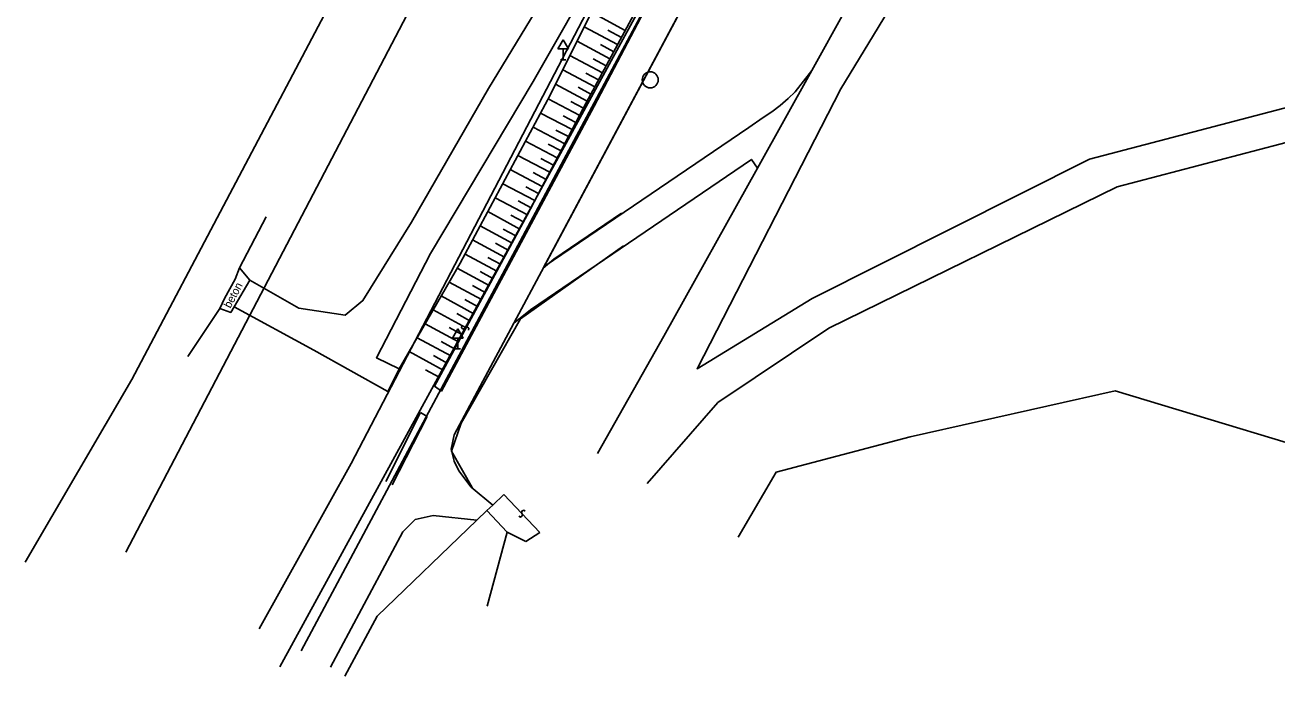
# Model space of a CAD drawing. Extents: x -747268 to -747068, y -964730 to -964532.
# Drawn here: x -747267.8 to -747150.9, y -964730 to -964669.2 of the extents above; entities that cross this region are included whole.
import ezdxf

# ---------------------------------------------------------------- set-up
doc = ezdxf.new("R2010")
doc.units = 0
for name, color, linetype in [('Bonity', 7, 'Continuous'), ('Obvody budov', 7, 'Continuous'), ('Vrstva 15', 7, 'Continuous'), ('Vrstva 16', 7, 'Continuous'), ('Vrstva 20', 7, 'Continuous'), ('Vrstva 27', 7, 'Continuous'), ('Vrstva 28', 7, 'Continuous')]:
    doc.layers.add(name, color=color, linetype=linetype)

msp = doc.modelspace()

# ---------------------------------------------------------------- linework, layer by layer
at = {"layer": 'Bonity'}
msp.add_lwpolyline([(-747212.14, -964686.73), (-747218.44, -964691.02)], dxfattribs=at)
at = {"layer": 'Obvody budov'}
for p, q in [((-747217.58, -964670.52), (-747218.08, -964671.39)), ((-747217.58, -964670.52), (-747217.08, -964671.39)), ((-747218.08, -964671.39), (-747217.08, -964671.39)), ((-747217.58, -964672.39), (-747217.58, -964671.39)), ((-747217.83, -964672.39), (-747217.33, -964672.39)), ((-747227.41, -964697.54), (-747227.91, -964698.41)), ((-747227.41, -964697.54), (-747226.91, -964698.41)), ((-747227.91, -964698.41), (-747226.91, -964698.41)), ((-747227.41, -964699.41), (-747227.41, -964698.41)), ((-747227.66, -964699.41), (-747227.16, -964699.41))]:
    msp.add_line(p, q, dxfattribs=at)
msp.add_circle((-747209.45, -964674.27), 0.75, dxfattribs=at)
at = {"layer": 'Vrstva 15'}
for points in [[(-747164.8, -964581.46), (-747168.98, -964589.75), (-747182.91, -964616.97), (-747186.63, -964624.1), (-747193.85, -964638.28), (-747194.38, -964638.56), (-747199.08, -964647.44), (-747204.82, -964658.33), (-747208.77, -964665.45), (-747214.7, -964676.73), (-747220.35, -964687.31), (-747228.95, -964703.36)], [(-747207.74, -964618.01), (-747209.42, -964620.7), (-747207.13, -964621.42), (-747205.64, -964619.2), (-747202.99, -964624.62), (-747199.45, -964632.07), (-747215.93, -964660.89), (-747224.57, -964675.08), (-747231.76, -964687.56), (-747236.28, -964694.89), (-747237.94, -964696.27), (-747242.26, -964695.59), (-747246.85, -964693), (-747247.82, -964691.84), (-747248.23, -964692.9)], [(-747212.14, -964686.73), (-747218.44, -964691.02), (-747219.46, -964691.87), (-747209.93, -964674.01), (-747202.82, -964660.7), (-747201.3, -964658.87), (-747199.71, -964658.58), (-747200.02, -964667.66)], [(-747232.9, -964701.27), (-747235.02, -964700.23), (-747229.96, -964690.49), (-747220.4, -964674.42), (-747214, -964663.21), (-747212.54, -964663.12)], [(-747226.09, -964712.35), (-747228.02, -964708.96), (-747227.1, -964706.36), (-747221.56, -964696.59), (-747211.96, -964689.78)], [(-747248.23, -964692.9), (-747249.2, -964694.71)], [(-747248.32, -964695.49), (-747246.85, -964693)], [(-747249.2, -964694.71), (-747249.65, -964695.64), (-747248.63, -964696), (-747248.32, -964695.49), (-747240.87, -964699.52), (-747233.96, -964703.39)], [(-747233.96, -964703.39), (-747232.9, -964701.27)], [(-747228.95, -964703.36), (-747229.61, -964702.9)], [(-747230.28, -964705.73), (-747233.55, -964712.11)], [(-747230.28, -964705.73), (-747230.91, -964705.35)]]:
    msp.add_lwpolyline(points, dxfattribs=at)
at = {"layer": 'Vrstva 16'}
for points in [[(-747232.9, -964701.27), (-747227.21, -964691.41), (-747218.79, -964675.69), (-747212.54, -964663.12)], [(-747209.31, -964665.03), (-747215.42, -964676.41), (-747220.94, -964686.92), (-747229.61, -964702.9)], [(-747211.79, -964669.66), (-747214.95, -964667.96)], [(-747212.5, -964670.98), (-747215.62, -964669.31)], [(-747213.21, -964672.3), (-747216.28, -964670.65)], [(-747212.15, -964670.32), (-747213.4, -964669.64)], [(-747212.86, -964671.64), (-747214.09, -964670.97)], [(-747213.92, -964673.62), (-747216.95, -964671.99)], [(-747213.57, -964672.96), (-747214.79, -964672.3)], [(-747214.63, -964674.94), (-747217.62, -964673.34)], [(-747214.28, -964674.28), (-747215.48, -964673.64)], [(-747215.34, -964676.26), (-747218.29, -964674.68)], [(-747214.99, -964675.6), (-747216.17, -964674.96)], [(-747216.04, -964677.59), (-747218.98, -964676.05)], [(-747215.69, -964676.93), (-747216.87, -964676.31)], [(-747216.74, -964678.92), (-747219.69, -964677.37)], [(-747216.39, -964678.26), (-747217.57, -964677.64)], [(-747217.44, -964680.25), (-747220.4, -964678.69)], [(-747218.13, -964681.57), (-747221.11, -964680.01)], [(-747217.09, -964679.58), (-747218.27, -964678.96)], [(-747217.78, -964680.91), (-747218.97, -964680.29)], [(-747218.83, -964682.9), (-747221.81, -964681.33)], [(-747218.48, -964682.24), (-747219.67, -964681.61)], [(-747219.53, -964684.23), (-747222.52, -964682.66)], [(-747219.18, -964683.57), (-747220.37, -964682.94)], [(-747220.22, -964685.56), (-747223.23, -964683.98)], [(-747219.88, -964684.89), (-747221.08, -964684.26)], [(-747220.92, -964686.89), (-747223.94, -964685.3)], [(-747220.57, -964686.22), (-747221.78, -964685.59)], [(-747221.64, -964688.21), (-747224.62, -964686.58)], [(-747221.28, -964687.55), (-747222.48, -964686.9)], [(-747247.82, -964691.84), (-747245.33, -964687.06)], [(-747222.35, -964689.52), (-747225.33, -964687.91)], [(-747223.07, -964690.84), (-747226.04, -964689.23)], [(-747221.99, -964688.86), (-747223.19, -964688.22)], [(-747223.78, -964692.16), (-747226.75, -964690.55)], [(-747222.71, -964690.18), (-747223.9, -964689.54)], [(-747223.43, -964691.5), (-747224.61, -964690.86)], [(-747224.5, -964693.48), (-747227.47, -964691.86)], [(-747224.14, -964692.82), (-747225.33, -964692.18)], [(-747225.21, -964694.8), (-747228.22, -964693.17)], [(-747224.86, -964694.14), (-747226.05, -964693.49)], [(-747225.93, -964696.12), (-747228.97, -964694.46)], [(-747225.57, -964695.46), (-747226.78, -964694.8)], [(-747249.65, -964695.64), (-747252.63, -964700.13)], [(-747226.65, -964697.43), (-747229.72, -964695.76)], [(-747226.29, -964696.78), (-747227.51, -964696.11)], [(-747227.36, -964698.75), (-747230.47, -964697.06)], [(-747227, -964698.09), (-747228.24, -964697.42)], [(-747228.08, -964700.07), (-747231.22, -964698.36)], [(-747227.72, -964699.41), (-747228.97, -964698.73)], [(-747228.79, -964701.39), (-747231.97, -964699.66)], [(-747228.43, -964700.73), (-747229.7, -964700.04)], [(-747229.15, -964702.05), (-747230.43, -964701.35)], [(-747230.91, -964705.35), (-747234.13, -964711.81)]]:
    msp.add_lwpolyline(points, dxfattribs=at)
at = {"layer": 'Vrstva 27'}
for p, q in [((-747194.37, -964673.41), (-747199.44, -964682.52)), ((-747222.18, -964697), (-747219.36, -964691.72)), ((-747224.7, -964714.51), (-747225.64, -964715.41))]:
    msp.add_line(p, q, dxfattribs=at)
for points in [[(-747258.43, -964718.4), (-747225.89, -964656.18), (-747178.58, -964571.79), (-747161.77, -964542.83)], [(-747245.97, -964725.57), (-747237.39, -964710.13), (-747213.15, -964663.66), (-747212.04, -964661.58), (-747205.52, -964649.38), (-747207.93, -964646.01), (-747172.64, -964585.56), (-747171.18, -964583.16), (-747172.38, -964582.51), (-747172.75, -964582.31), (-747169.52, -964576.73), (-747168.08, -964577.53), (-747165.21, -964574.13), (-747160.86, -964564.14), (-747155.16, -964551.47), (-747155.48, -964551.37), (-747155.09, -964550.12), (-747154.28, -964550.33), (-747154.06, -964549.5), (-747153.36, -964547.04)], [(-747242.05, -964727.61), (-747230.16, -964705.36), (-747208.97, -964665.66), (-747208.88, -964665.32), (-747209.05, -964664.92), (-747208.39, -964663.57), (-747207.91, -964663.49), (-747207.6, -964663.09), (-747199.41, -964647.48), (-747199.14, -964646.95), (-747194.94, -964639.04), (-747194.8, -964638.66), (-747194.08, -964638.4), (-747193.89, -964638.17), (-747178.12, -964607.48), (-747165.52, -964582.92), (-747162.81, -964577.62), (-747161.38, -964574.2), (-747160.49, -964571.42), (-747153.77, -964550.39), (-747154.12, -964550.42), (-747153.81, -964549.44), (-747153.11, -964547.25)], [(-747149.73, -964549.09), (-747149.93, -964549.71), (-747150.35, -964549.8), (-747157.75, -964573.23), (-747158.53, -964575.6), (-747159.7, -964578.37), (-747163.23, -964585.33), (-747175.42, -964609.03), (-747186.84, -964631.22), (-747187.01, -964633.47), (-747185.08, -964635.94), (-747196.29, -964656.98), (-747198.54, -964658.68), (-747199.84, -964658.63), (-747201.84, -964659.38), (-747202.78, -964660.64), (-747203.73, -964662.42), (-747219.36, -964691.72)], [(-747179.78, -964638.67), (-747191.19, -964659.92), (-747188.06, -964662.04), (-747194.37, -964673.41)], [(-747170.03, -964639.52), (-747191.65, -964675.11), (-747205.07, -964701.27), (-747194.33, -964694.71), (-747168.43, -964681.69), (-747141.95, -964674.74), (-747119.57, -964669.71), (-747114.21, -964668.06), (-747110.99, -964665.85), (-747107.13, -964660.6)], [(-747104.3, -964675.97), (-747110.73, -964672.35), (-747113.2, -964673.81), (-747141.15, -964677.79), (-747165.83, -964684.28), (-747192.76, -964697.48), (-747203.13, -964704.43), (-747209.73, -964712)], [(-747219.36, -964691.72), (-747200.23, -964678.71), (-747198.91, -964677.79), (-747198.11, -964677.27), (-747197.31, -964676.67), (-747196.56, -964676.02), (-747195.92, -964675.4), (-747194.37, -964673.41)], [(-747222.18, -964697), (-747220.64, -964695.77), (-747200, -964681.71), (-747199.44, -964682.52)], [(-747199.44, -964682.52), (-747208.18, -964698.23), (-747214.38, -964709.19)], [(-747224.7, -964714.51), (-747224.16, -964714), (-747226.16, -964712.32), (-747227.33, -964710.79), (-747227.75, -964709.91), (-747228.03, -964708.77), (-747227.76, -964707.45), (-747222.18, -964697)], [(-747201.23, -964716.99), (-747197.7, -964710.92), (-747185.17, -964707.62), (-747166.03, -964703.32), (-747141.08, -964710.85), (-747134.49, -964709.31), (-747125.59, -964712.6), (-747114.89, -964709.21), (-747113.01, -964712.26), (-747107.67, -964711.37)], [(-747225.64, -964715.41), (-747229.73, -964714.98), (-747231.4, -964715.34), (-747232.57, -964716.49), (-747239.31, -964729.13)], [(-747224.67, -964723.45), (-747222.81, -964716.53), (-747224.7, -964714.51)], [(-747225.64, -964715.41), (-747234.96, -964724.38), (-747237.96, -964729.97)]]:
    msp.add_lwpolyline(points, dxfattribs=at)
at = {"layer": 'Vrstva 28'}
for p, q in [((-747257.86, -964702.26), (-747231.87, -964652.97)), ((-747209.18, -964665.33), (-747244.03, -964729.12)), ((-747267.84, -964719.33), (-747257.86, -964702.26)), ((-747223.12, -964713.02), (-747224.16, -964714)), ((-747219.76, -964716.57), (-747223.12, -964713.02)), ((-747222.81, -964716.53), (-747221.08, -964717.4)), ((-747221.08, -964717.4), (-747219.76, -964716.57))]:
    msp.add_line(p, q, dxfattribs=at)
for points in [[(-747226.41, -964697.66), (-747226.38, -964697.5), (-747226.49, -964697.38), (-747226.64, -964697.37), (-747226.83, -964697.54), (-747226.99, -964697.53), (-747227.08, -964697.4), (-747227.05, -964697.25)], [(-747221.72, -964715.04), (-747221.58, -964715.12), (-747221.43, -964715.05), (-747221.38, -964714.91), (-747221.48, -964714.68), (-747221.42, -964714.54), (-747221.27, -964714.49), (-747221.14, -964714.56)]]:
    msp.add_lwpolyline(points, dxfattribs=at)

# ---------------------------------------------------------------- texts
at = {"layer": 'Vrstva 20'}
msp.add_text('beton', height=0.75, rotation=61.8126, dxfattribs=at).set_placement((-747248.67, -964695.67))

doc.saveas('drawing.dxf')
